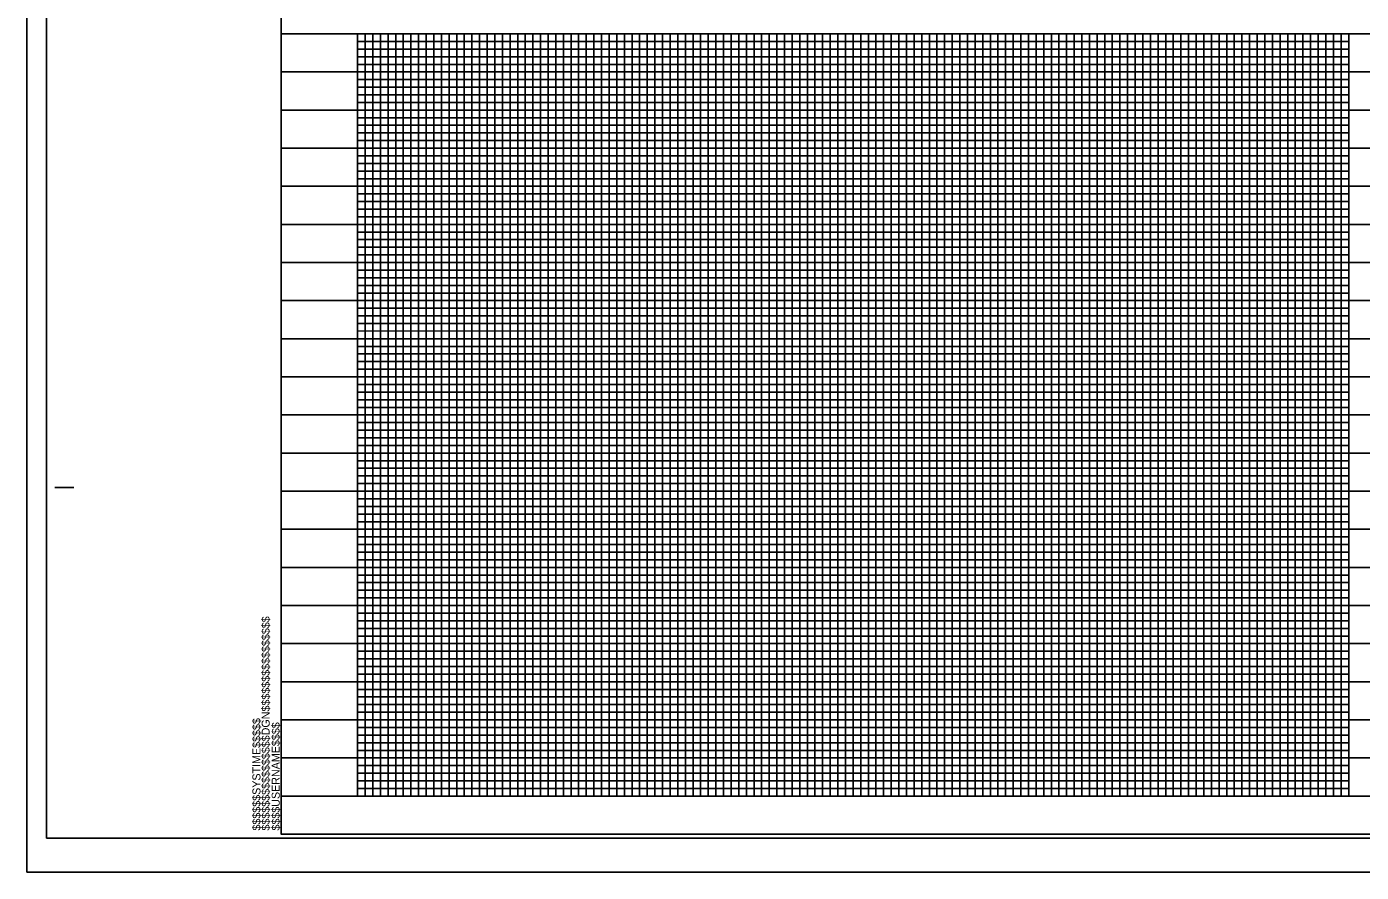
# Model space of a CAD drawing. Extents: x 1019474 to 1021158, y 503201 to 504732.
# Drawn here: x 1019474 to 1020350, y 503201 to 503755 of the extents above; entities that cross this region are included whole.
import ezdxf

# ---------------------------------------------------------------- set-up
doc = ezdxf.new("R2010")
doc.units = 0
for name, color, linetype in [('Sheet Cutting Line CELL', 7, 'Continuous'), ('Sheet Layout Profile Border Port 2', 7, 'Continuous'), ('Sheet Plot Border Inside CELL', 7, 'Continuous'), ('Sheet Plot Border Outside CELL', 7, 'Continuous'), ('Sheet Profile CELL', 7, 'Continuous'), ('Sheet Profile Grid Major CELL', 7, 'Continuous'), ('Sheet Profile Grid Middle CELL', 7, 'Continuous'), ('Sheet Profile Grid Minor CELL', 7, 'Continuous')]:
    doc.layers.add(name, color=color, linetype=linetype)

msp = doc.modelspace()

# ---------------------------------------------------------------- linework, layer by layer
at = {"layer": 'Sheet Cutting Line CELL'}
for p, q in [((1019474.22, 504300.7), (1019474.22, 503200.7)), ((1019474.22, 503200.7), (1021158.22, 503200.7))]:
    msp.add_line(p, q, dxfattribs=at)
at = {"layer": 'Sheet Layout Profile Border Port 2'}
msp.add_lwpolyline([(1019691.22, 503750.7), (1021091.22, 503750.7), (1021091.22, 503250.7), (1019691.22, 503250.7)], close=True, dxfattribs=at)
at = {"layer": 'Sheet Plot Border Inside CELL'}
msp.add_lwpolyline([(1019487.22, 503223.15), (1021153.72, 503223.15), (1021153.72, 504278.25), (1019487.22, 504278.25)], close=True, dxfattribs=at)
at = {"layer": 'Sheet Plot Border Outside CELL'}
msp.add_lwpolyline([(1019474.22, 503200.7), (1021158.22, 503200.7), (1021158.22, 504300.7), (1019474.22, 504300.7)], close=True, dxfattribs=at)
at = {"layer": 'Sheet Profile CELL'}
for p, q in [((1019641.22, 503750.7), (1021141.22, 503750.7)), ((1019492.72, 503453.2), (1019505.22, 503453.2)), ((1021141.22, 503250.7), (1019641.22, 503250.7)), ((1019641.22, 503225.7), (1021141.22, 503225.7)), ((1019641.22, 503225.7), (1019641.22, 503225.7)), ((1019641.22, 503225.7), (1019641.22, 503225.7)), ((1019641.22, 503225.7), (1019641.22, 503225.7)), ((1019641.22, 503225.7), (1019641.22, 503225.7)), ((1019641.22, 503225.7), (1019641.22, 503225.7)), ((1019641.22, 503225.7), (1019641.22, 503225.7)), ((1019641.22, 503225.7), (1019641.22, 503225.7))]:
    msp.add_line(p, q, dxfattribs=at)
msp.add_lwpolyline([(1021141.22, 504275.7), (1019641.22, 504275.7), (1019641.22, 503225.7), (1021141.22, 503225.7)], close=True, dxfattribs=at)
msp.add_lwpolyline([(1019678.72, 503225.7), (1019678.72, 503225.7)], dxfattribs=at)
at = {"layer": 'Sheet Profile Grid Major CELL'}
for p, q in [((1020141.22, 503750.7), (1020191.22, 503750.7)), ((1020241.22, 503750.7), (1020291.22, 503750.7)), ((1020341.22, 503750.7), (1020391.22, 503750.7)), ((1019641.22, 503250.7), (1019641.22, 503250.7))]:
    msp.add_line(p, q, dxfattribs=at)
for points in [[(1019691.22, 503750.7), (1019691.22, 503250.7), (1019741.22, 503250.7), (1019741.22, 503750.7), (1019791.22, 503750.7), (1019791.22, 503250.7), (1019841.22, 503250.7), (1019841.22, 503750.7), (1019891.22, 503750.7), (1019891.22, 503250.7), (1019941.22, 503250.7), (1019941.22, 503750.7), (1019991.22, 503750.7), (1019991.22, 503250.7), (1020041.22, 503250.7), (1020041.22, 503750.7), (1020091.22, 503750.7), (1020091.22, 503250.7), (1020141.22, 503250.7), (1020141.22, 503750.7), (1020191.22, 503750.7), (1020191.22, 503250.7), (1020241.22, 503250.7), (1020241.22, 503750.7), (1020291.22, 503750.7), (1020291.22, 503250.7), (1020341.22, 503250.7), (1020341.22, 503750.7), (1020391.22, 503750.7)], [(1021141.22, 503700.7), (1019641.22, 503700.7)], [(1021141.22, 503650.7), (1019641.22, 503650.7), (1019641.22, 503600.7), (1021141.22, 503600.7)], [(1021141.22, 503550.7), (1019641.22, 503550.7), (1019641.22, 503500.7), (1021141.22, 503500.7)], [(1021141.22, 503450.7), (1019641.22, 503450.7), (1019641.22, 503400.7), (1021141.22, 503400.7)], [(1021141.22, 503350.7), (1019641.22, 503350.7), (1019641.22, 503350.7), (1019641.22, 503300.7), (1021141.22, 503300.7)], [(1021141.22, 503250.7), (1019641.22, 503250.7)]]:
    msp.add_lwpolyline(points, dxfattribs=at)
at = {"layer": 'Sheet Profile Grid Middle CELL'}
for points in [[(1019666.22, 503750.7), (1019716.22, 503750.7), (1019716.22, 503250.7), (1019766.22, 503250.7), (1019766.22, 503750.7), (1019816.22, 503750.7), (1019816.22, 503250.7), (1019866.22, 503250.7), (1019866.22, 503750.7), (1019916.22, 503750.7), (1019916.22, 503250.7), (1019966.22, 503250.7), (1019966.22, 503750.7), (1020016.22, 503750.7), (1020016.22, 503250.7), (1020066.22, 503250.7), (1020066.22, 503750.7), (1020116.22, 503750.7), (1020116.22, 503250.7), (1020166.22, 503250.7), (1020166.22, 503750.7), (1020216.22, 503750.7), (1020216.22, 503250.7), (1020266.22, 503250.7), (1020266.22, 503250.7), (1020266.22, 503750.7), (1020316.22, 503750.7), (1020316.22, 503250.7), (1020341.22, 503250.7)], [(1019641.22, 503725.7), (1021141.22, 503725.7)], [(1021141.22, 503675.7), (1019641.22, 503675.7), (1019641.22, 503625.7), (1021141.22, 503625.7)], [(1021141.22, 503575.7), (1019641.22, 503575.7), (1019641.22, 503525.7), (1021141.22, 503525.7)], [(1021141.22, 503475.7), (1019641.22, 503475.7), (1019641.22, 503425.7), (1021141.22, 503425.7)], [(1021141.22, 503375.7), (1019641.22, 503375.7), (1019641.22, 503325.7), (1021141.22, 503325.7)], [(1021141.22, 503275.7), (1019641.22, 503275.7)]]:
    msp.add_lwpolyline(points, dxfattribs=at)
at = {"layer": 'Sheet Profile Grid Minor CELL'}
for p, q in [((1019691.22, 503745.7), (1020341.22, 503745.7)), ((1020341.22, 503740.7), (1019691.22, 503740.7)), ((1019691.22, 503735.7), (1020341.22, 503735.7)), ((1020341.22, 503730.7), (1019691.22, 503730.7)), ((1019691.22, 503720.7), (1020341.22, 503720.7)), ((1020341.22, 503715.7), (1019691.22, 503715.7)), ((1019691.22, 503710.7), (1020341.22, 503710.7)), ((1020341.22, 503705.7), (1019691.22, 503705.7)), ((1019691.22, 503695.7), (1020341.22, 503695.7)), ((1020341.22, 503690.7), (1019691.22, 503690.7)), ((1019691.22, 503685.7), (1020341.22, 503685.7)), ((1020341.22, 503680.7), (1019691.22, 503680.7)), ((1019691.22, 503670.7), (1020341.22, 503670.7)), ((1020341.22, 503665.7), (1019691.22, 503665.7)), ((1019691.22, 503660.7), (1020341.22, 503660.7)), ((1020341.22, 503655.7), (1019691.22, 503655.7)), ((1019691.22, 503645.7), (1020341.22, 503645.7)), ((1020341.22, 503640.7), (1019691.22, 503640.7)), ((1019691.22, 503635.7), (1020341.22, 503635.7)), ((1020341.22, 503630.7), (1019691.22, 503630.7)), ((1019691.22, 503620.7), (1020341.22, 503620.7)), ((1020341.22, 503615.7), (1019691.22, 503615.7)), ((1019691.22, 503610.7), (1020341.22, 503610.7)), ((1020341.22, 503605.7), (1019691.22, 503605.7)), ((1019691.22, 503595.7), (1020341.22, 503595.7)), ((1019691.22, 503590.7), (1020341.22, 503590.7)), ((1019691.22, 503585.7), (1020341.22, 503585.7)), ((1020341.22, 503580.7), (1019691.22, 503580.7)), ((1019691.22, 503570.7), (1020341.22, 503570.7)), ((1020341.22, 503565.7), (1019691.22, 503565.7)), ((1019691.22, 503560.7), (1020341.22, 503560.7)), ((1020341.22, 503555.78), (1019691.22, 503555.85)), ((1019691.22, 503545.7), (1020341.22, 503545.7)), ((1020341.22, 503540.7), (1019691.22, 503540.7)), ((1019691.22, 503535.7), (1020341.22, 503535.7)), ((1020341.22, 503530.7), (1019691.22, 503530.7)), ((1019691.22, 503520.7), (1020341.22, 503520.7)), ((1020341.22, 503515.7), (1019691.22, 503515.7)), ((1019691.22, 503510.7), (1020341.22, 503510.7)), ((1020341.22, 503505.7), (1019691.22, 503505.7)), ((1019691.22, 503495.7), (1020341.22, 503495.7)), ((1020341.22, 503490.7), (1019691.22, 503490.7)), ((1019691.22, 503485.7), (1020341.22, 503485.7)), ((1020341.22, 503480.7), (1019691.22, 503480.7)), ((1019691.22, 503470.7), (1020341.22, 503470.7)), ((1020341.22, 503465.7), (1019691.22, 503465.7)), ((1019691.22, 503460.7), (1020341.22, 503460.7)), ((1020341.22, 503455.7), (1019691.22, 503455.7)), ((1019691.22, 503445.7), (1020341.22, 503445.7)), ((1020341.22, 503440.7), (1019691.22, 503440.7)), ((1019691.22, 503435.7), (1020341.22, 503435.7)), ((1020341.22, 503430.7), (1019691.22, 503430.7)), ((1019691.22, 503420.7), (1020341.22, 503420.7)), ((1020341.22, 503415.7), (1019691.22, 503415.7)), ((1019691.22, 503410.7), (1020341.22, 503410.7)), ((1020341.22, 503405.7), (1019691.22, 503405.7)), ((1019691.22, 503395.7), (1020341.22, 503395.7)), ((1020341.22, 503390.7), (1019691.22, 503390.7)), ((1019691.22, 503385.7), (1020341.22, 503385.7)), ((1020341.22, 503380.7), (1019691.22, 503380.7)), ((1019691.22, 503370.7), (1020341.22, 503370.7)), ((1020341.22, 503365.7), (1019691.22, 503365.7)), ((1019691.22, 503360.7), (1020341.22, 503360.7)), ((1020341.22, 503355.7), (1019691.22, 503355.7)), ((1019691.22, 503345.7), (1020341.22, 503345.7)), ((1020341.22, 503340.7), (1019691.22, 503340.7)), ((1019691.22, 503335.7), (1020341.22, 503335.7)), ((1020341.22, 503330.7), (1019691.22, 503330.7)), ((1019691.22, 503320.7), (1020341.22, 503320.7)), ((1020341.22, 503315.7), (1019691.22, 503315.7)), ((1019691.22, 503310.7), (1020341.22, 503310.7)), ((1020341.22, 503305.7), (1019691.22, 503305.7)), ((1019691.22, 503295.7), (1020341.22, 503295.7)), ((1020341.22, 503290.7), (1019691.22, 503290.7)), ((1019691.22, 503285.7), (1020341.22, 503285.7)), ((1020341.22, 503280.7), (1019691.22, 503280.7)), ((1019691.22, 503270.7), (1020341.22, 503270.7)), ((1020341.22, 503265.7), (1019691.22, 503265.7)), ((1019691.22, 503260.7), (1020341.22, 503260.7)), ((1019691.22, 503255.7), (1020341.22, 503255.7))]:
    msp.add_line(p, q, dxfattribs=at)
for points in [[(1019691.22, 503750.7), (1019696.22, 503750.7), (1019696.22, 503250.7), (1019701.22, 503250.7), (1019701.22, 503750.7), (1019706.22, 503750.7), (1019706.22, 503250.7), (1019711.22, 503250.7), (1019711.22, 503750.7), (1019721.22, 503750.7), (1019721.22, 503250.7), (1019726.22, 503250.7), (1019726.22, 503750.7), (1019731.22, 503750.7), (1019731.22, 503250.7), (1019736.22, 503250.7), (1019746.22, 503250.7), (1019751.22, 503250.7), (1019751.22, 503750.7), (1019756.22, 503750.7), (1019756.22, 503250.7), (1019761.22, 503250.7), (1019761.22, 503750.7), (1019771.22, 503750.7), (1019771.22, 503250.7), (1019776.22, 503250.7), (1019776.22, 503750.7), (1019781.22, 503750.7), (1019781.22, 503250.7), (1019786.22, 503250.7), (1019786.22, 503750.7), (1019796.22, 503750.7), (1019796.22, 503250.7), (1019801.22, 503250.7), (1019801.22, 503750.7), (1019806.22, 503750.7), (1019806.22, 503250.7), (1019811.22, 503250.7), (1019811.22, 503750.7), (1019821.22, 503750.7), (1019821.22, 503250.7), (1019826.22, 503250.7), (1019826.22, 503750.7), (1019831.22, 503750.7), (1019831.22, 503250.7), (1019836.22, 503250.7), (1019836.22, 503750.7), (1019846.22, 503750.7), (1019846.22, 503250.7), (1019851.22, 503250.7), (1019851.22, 503750.7), (1019856.22, 503750.7), (1019856.22, 503250.7), (1019861.22, 503250.7), (1019861.22, 503750.7), (1019871.22, 503750.7), (1019871.22, 503250.7), (1019876.22, 503250.7), (1019876.22, 503750.7), (1019881.22, 503750.7), (1019881.22, 503250.7), (1019886.22, 503250.7), (1019886.22, 503750.7), (1019896.22, 503750.7), (1019896.22, 503250.7), (1019901.22, 503250.7), (1019901.22, 503750.7), (1019906.22, 503750.7), (1019906.22, 503250.7)], [(1019736.22, 503250.7), (1019736.22, 503750.7), (1019746.22, 503750.7), (1019746.22, 503250.7)], [(1019906.22, 503250.7), (1019911.22, 503250.7), (1019911.22, 503750.7), (1019921.22, 503750.7), (1019921.22, 503250.7), (1019926.22, 503250.7), (1019926.22, 503750.7), (1019931.22, 503750.7), (1019931.22, 503250.7), (1019936.22, 503250.7), (1019936.22, 503750.7), (1019946.22, 503750.7), (1019946.22, 503250.7), (1019951.22, 503250.7), (1019951.22, 503750.7), (1019956.22, 503750.7), (1019956.22, 503250.7), (1019961.22, 503250.7), (1019961.22, 503750.7), (1019971.22, 503750.7), (1019971.22, 503250.7), (1019976.22, 503250.7), (1019976.22, 503750.7), (1019981.22, 503750.7), (1019981.22, 503250.7), (1019986.22, 503250.7), (1019986.22, 503750.7), (1019996.22, 503750.7), (1019996.22, 503250.7), (1020001.22, 503250.7), (1020001.22, 503750.7), (1020006.22, 503750.7), (1020006.22, 503250.7), (1020011.22, 503250.7), (1020011.22, 503750.7), (1020021.22, 503750.7), (1020021.22, 503250.7), (1020026.22, 503250.7), (1020026.22, 503750.7), (1020031.22, 503750.7), (1020031.22, 503250.7), (1020036.22, 503250.7), (1020036.22, 503750.7), (1020046.22, 503750.7), (1020046.22, 503250.7), (1020051.22, 503250.7), (1020051.22, 503750.7), (1020056.22, 503750.7), (1020056.22, 503250.7), (1020061.22, 503250.7), (1020061.22, 503750.7), (1020071.22, 503750.7), (1020071.22, 503250.7), (1020076.22, 503250.7), (1020076.22, 503750.7), (1020081.22, 503750.7), (1020081.22, 503250.7), (1020086.22, 503250.7), (1020086.22, 503750.7), (1020096.22, 503750.7), (1020096.22, 503250.7), (1020101.22, 503250.7), (1020101.22, 503750.7), (1020106.22, 503750.7), (1020106.22, 503250.7), (1020111.22, 503250.7), (1020111.22, 503750.7), (1020121.22, 503750.7), (1020121.22, 503250.7), (1020126.22, 503250.7), (1020126.22, 503750.7), (1020131.22, 503750.7), (1020131.22, 503250.7), (1020136.22, 503250.7), (1020136.22, 503750.7), (1020146.22, 503750.7), (1020146.22, 503250.7), (1020151.22, 503250.7), (1020151.22, 503750.7), (1020156.22, 503750.7), (1020156.22, 503250.7), (1020161.22, 503250.7), (1020161.22, 503750.7), (1020171.22, 503750.7), (1020171.22, 503250.7), (1020176.22, 503250.7), (1020176.22, 503750.7), (1020181.22, 503750.7), (1020181.22, 503250.7), (1020186.22, 503250.7), (1020186.22, 503750.7), (1020196.22, 503750.7), (1020196.22, 503250.7), (1020201.22, 503250.7), (1020201.22, 503750.7), (1020206.22, 503750.7), (1020206.22, 503250.7), (1020211.22, 503250.7), (1020211.22, 503750.7), (1020221.22, 503750.7)], [(1020221.22, 503750.7), (1020221.22, 503250.7), (1020226.22, 503250.7), (1020226.22, 503750.7), (1020231.22, 503750.7), (1020231.22, 503250.7), (1020236.22, 503250.7), (1020236.22, 503750.7), (1020246.22, 503750.7), (1020246.22, 503250.7), (1020251.22, 503250.7), (1020251.22, 503750.7), (1020256.22, 503750.7), (1020256.22, 503250.7), (1020261.22, 503250.7), (1020261.22, 503750.7), (1020271.22, 503750.7), (1020271.22, 503250.7), (1020276.22, 503250.7), (1020276.22, 503750.7), (1020281.22, 503750.7), (1020281.22, 503250.7), (1020286.22, 503250.7), (1020286.22, 503750.7), (1020296.22, 503750.7), (1020296.22, 503250.7), (1020301.22, 503250.7), (1020301.22, 503750.7), (1020306.22, 503750.7), (1020306.22, 503250.7), (1020311.22, 503250.7), (1020311.22, 503750.7), (1020321.22, 503750.7), (1020321.22, 503250.7), (1020326.22, 503250.7), (1020326.22, 503750.7), (1020331.22, 503750.7), (1020331.22, 503250.7), (1020336.22, 503250.7), (1020336.22, 503750.7), (1020341.22, 503750.7)]]:
    msp.add_lwpolyline(points, dxfattribs=at)

# ---------------------------------------------------------------- texts
at = {"layer": 'Sheet Profile CELL'}
for s, p in [('$$$$$$$$$$$$$$$$DGN$$$$$$$$$$$$$$$$', (1019633.58, 503228.07)), ('$$$$$$SYSTIME$$$$$', (1019627.53, 503228.07)), ('$$$$USERNAME$$$$', (1019640.16, 503228.08))]:
    msp.add_text(s, height=5.25, rotation=90, dxfattribs=at).set_placement(p)

doc.saveas('drawing.dxf')
